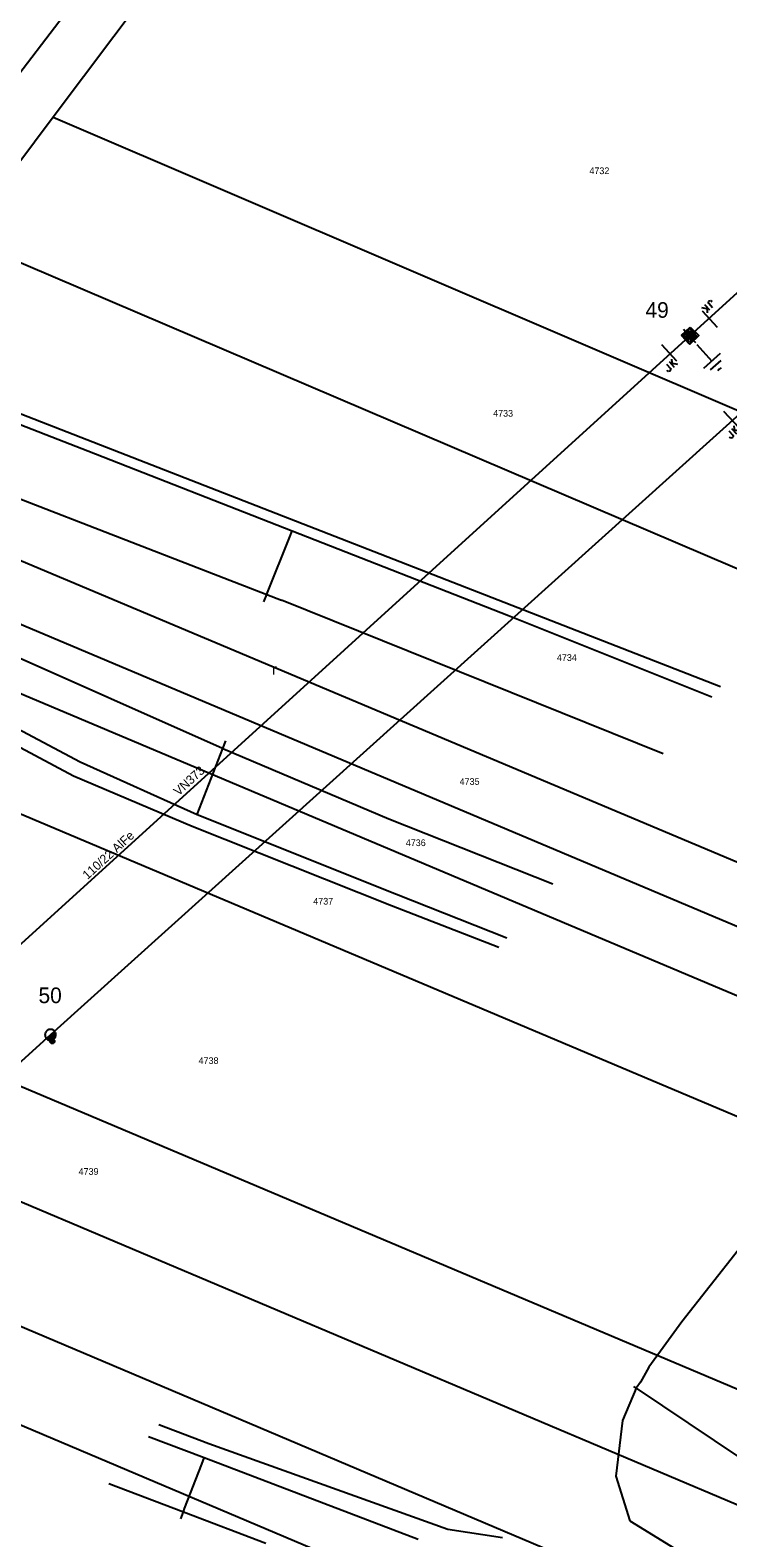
# Model space of a CAD drawing. Extents: x -540150 to -533593, y -1185082 to -1180066.
# Drawn here: x -536094 to -536015.9, y -1182345.7 to -1182176.7 of the extents above; entities that cross this region are included whole.
import ezdxf

# ---------------------------------------------------------------- set-up
doc = ezdxf.new("R2010")
doc.units = 0
for name, color, linetype in [('KN_HRAN_PARCEL', 7, 'Continuous'), ('KN_PARC_Č', 7, 'Continuous'), ('Vrstva 1', 7, 'Continuous'), ('Vrstva 13', 7, 'Continuous'), ('Vrstva 14', 7, 'Continuous'), ('Vrstva 15', 7, 'Continuous'), ('Vrstva 18', 7, 'Continuous'), ('Vrstva 2', 7, 'Continuous'), ('Vrstva 25', 7, 'Continuous'), ('Vrstva 3', 7, 'Continuous'), ('Vrstva 36', 7, 'Continuous'), ('Vrstva 7', 7, 'Continuous')]:
    doc.layers.add(name, color=color, linetype=linetype)

# ---------------------------------------------------------------- blocks, each defined once
blk = doc.blocks.new('VN840')
at = {"layer": 'Vrstva 15'}
for points in [[(-0.01, 1.41), (-0.01, -1.09)], [(-1.51, -1.24), (-1.51, -1.15)], [(-1.48, -1.35), (-1.51, -1.24)], [(-1.33, -1.42), (-1.48, -1.35)], [(-1.27, -1.42), (-1.33, -1.42)], [(-1.13, -1.35), (-1.27, -1.42)], [(-1.09, -1.24), (-1.13, -1.35)], [(-1.09, -0.59), (-1.09, -1.24)], [(-0.68, -0.59), (-0.68, -1.42)], [(-0.68, -1.11), (-0.27, -0.59)], [(-0.54, -0.94), (-0.2, -1.42)]]:
    blk.add_lwpolyline(points, dxfattribs=at)
blk = doc.blocks.new('VN440')
at = {"layer": 'Vrstva 2'}
for points in [[(1.22, 0), (1.21, 0.13), (1.19, 0.25), (1.16, 0.38), (1.11, 0.5), (1.05, 0.61), (0.98, 0.72), (0.9, 0.82), (0.81, 0.91), (0.71, 0.99), (0.6, 1.06), (0.49, 1.12), (0.37, 1.16), (0.25, 1.2), (0.12, 1.22), (-0.01, 1.22), (-0.14, 1.22), (-0.26, 1.2), (-0.39, 1.16), (-0.51, 1.12), (-0.62, 1.06), (-0.73, 0.99), (-0.83, 0.91), (-0.92, 0.82), (-1, 0.72), (-1.07, 0.61), (-1.13, 0.5), (-1.18, 0.38), (-1.21, 0.25), (-1.23, 0.13), (-1.24, 0), (-1.23, -0.13), (-1.21, -0.26), (-1.18, -0.38), (-1.13, -0.5), (-1.07, -0.62), (-1, -0.73), (-0.92, -0.83), (-0.83, -0.92), (-0.73, -1), (-0.62, -1.07), (-0.51, -1.13), (-0.39, -1.17), (-0.26, -1.2), (-0.14, -1.23), (-0.01, -1.23), (0.12, -1.23), (0.25, -1.2), (0.37, -1.17), (0.49, -1.13), (0.6, -1.07), (0.71, -1), (0.81, -0.92), (0.9, -0.83), (0.98, -0.73), (1.05, -0.62), (1.11, -0.5), (1.16, -0.38), (1.19, -0.26), (1.21, -0.13), (1.22, 0)], [(-1.24, 0), (1.22, 0)], [(-1.18, -0.34), (1.1, -0.34)], [(-1.01, -0.63), (0.97, -0.63)], [(-0.74, -0.92), (0.68, -0.92)]]:
    blk.add_lwpolyline(points, dxfattribs=at)
blk = doc.blocks.new('VN810')
at = {"layer": 'Vrstva 14'}
for points in [[(0, -1.25), (0, -3.75)], [(1.25, -3.75), (-1.25, -3.75)], [(0.77, -4.37), (-0.8, -4.37)], [(0, -5), (-0.25, -5)], [(0.27, -5), (0, -5)]]:
    blk.add_lwpolyline(points, dxfattribs=at)
blk = doc.blocks.new('VN470')
at = {"layer": 'Vrstva 2'}
for points in [[(-1.23, 1.22), (1.23, 1.22)], [(-1.23, -1.23), (-1.23, 1.22)], [(-0.92, 0.9), (0.92, 0.9)], [(-0.92, -0.95), (-0.92, 0.9)], [(-0.61, 0.61), (0.61, 0.61)], [(-0.61, -0.62), (-0.61, 0.61)], [(-0.31, -0.27), (-0.31, 0.34)], [(-0.31, 0.34), (0.31, 0.34)], [(0, 1.22), (0, 1.97)], [(0.31, 0.34), (0.31, -0.27)], [(0.61, 0.61), (0.61, -0.62)], [(0.92, 0.9), (0.92, -0.95)], [(1.23, 1.22), (1.23, -1.23)], [(1.23, -1.23), (-1.23, -1.23)], [(0.92, -0.95), (-0.92, -0.95)], [(0.61, -0.62), (-0.61, -0.62)], [(0.31, -0.27), (-0.31, -0.27)], [(0, -1.23), (0, -1.98)]]:
    blk.add_lwpolyline(points, dxfattribs=at)

msp = doc.modelspace()

# ---------------------------------------------------------------- linework, layer by layer
at = {"layer": 'KN_HRAN_PARCEL'}
for p, q in [((-536075.77, -1182165.61), (-536091.46, -1182186.49)), ((-536091.46, -1182186.49), (-536101.6, -1182200.04)), ((-536091.46, -1182186.49), (-535990.58, -1182229.75)), ((-536101.6, -1182200.04), (-535965.35, -1182258.21)), ((-536120.65, -1182225.43), (-535972.96, -1182287.61)), ((-536124.53, -1182230.88), (-535974.77, -1182294.08)), ((-536129.02, -1182236.75), (-535976.56, -1182301.1)), ((-536136.67, -1182246.99), (-535979.71, -1182313.28)), ((-536154.1, -1182270.11), (-535986.76, -1182340.88)), ((-535989.8, -1182352.58), (-536161.48, -1182279.94)), ((-536169.4, -1182290.52), (-535993.07, -1182365.17)), ((-536175.67, -1182298.88), (-535995.6, -1182375.13))]:
    msp.add_line(p, q, dxfattribs=at)
at = {"layer": 'Vrstva 1'}
for points in [[(-535558.37, -1181516.47), (-535557.88, -1181544.08), (-535587.84, -1181626.35), (-535619.52, -1181709.12), (-535651.77, -1181794.03), (-535681.12, -1181869.54), (-535710.09, -1181945.05), (-535783.95, -1182011.48), (-535866.19, -1182086.36), (-535938.34, -1182149.87), (-536013.11, -1182218.39), (-536091.77, -1182289.3), (-536171.39, -1182361.64), (-536250.64, -1182434.05), (-536331.09, -1182507.05), (-536410.34, -1182579.17), (-536496.48, -1182657.64), (-536561.1, -1182716.88), (-536627.07, -1182777.54), (-536686.64, -1182832.24), (-536719.16, -1182861.03)], [(-536097.51, -1182281.3), (-536020.22, -1182211.02), (-535949.21, -1182146.34), (-535873.11, -1182077.36)]]:
    msp.add_lwpolyline(points, dxfattribs=at)
at = {"layer": 'Vrstva 14'}
for p, q in [((-536101.68, -1182189.98), (-536088.77, -1182173.09)), ((-536109.43, -1182215.35), (-536087.58, -1182223.88)), ((-536087.58, -1182223.88), (-536064.7, -1182232.83)), ((-536064.7, -1182232.83), (-536040.49, -1182242.34)), ((-536067.89, -1182240.81), (-536067.56, -1182239.98)), ((-536067.56, -1182239.98), (-536067.47, -1182239.75)), ((-536108.96, -1182240.97), (-536072.51, -1182257.2)), ((-536040.49, -1182242.34), (-536017.72, -1182251.43)), ((-536100.05, -1182252.56), (-536088.45, -1182258.71)), ((-536089.2, -1182260.31), (-536100.91, -1182254.06)), ((-536072.46, -1182257.22), (-536072.13, -1182256.36)), ((-536088.45, -1182258.71), (-536075.36, -1182264.63)), ((-536075.92, -1182265.97), (-536089.2, -1182260.31)), ((-536075.36, -1182264.63), (-536053.03, -1182273.54)), ((-536053.89, -1182265.1), (-536035.51, -1182272.37)), ((-536053.58, -1182274.87), (-536075.92, -1182265.97)), ((-536053.03, -1182273.54), (-536040.67, -1182278.45)), ((-536041.59, -1182279.53), (-536053.58, -1182274.87)), ((-536022.87, -1182323.92), (-536024.77, -1182326.53)), ((-536026.2, -1182328.9), (-536027.72, -1182332.52)), ((-536079.65, -1182332.96), (-536074.03, -1182335.09)), ((-536027.72, -1182332.52), (-536028.47, -1182338.74)), ((-536074.56, -1182336.7), (-536080.81, -1182334.33)), ((-536074.03, -1182335.09), (-536047.3, -1182344.7)), ((-536050.61, -1182345.86), (-536074.56, -1182336.7)), ((-536028.47, -1182338.74), (-536026.91, -1182343.76)), ((-536077.19, -1182343.51), (-536076.89, -1182342.73)), ((-536076.89, -1182342.73), (-536076.76, -1182342.38)), ((-536047.3, -1182344.7), (-536041.16, -1182345.63)), ((-536026.91, -1182343.76), (-536021.37, -1182347.16))]:
    msp.add_line(p, q, dxfattribs=at)
for points in [[(-536140.4, -1182211.72), (-536112.24, -1182222.65), (-536067.56, -1182239.98), (-536065.92, -1182240.61)], [(-536108.24, -1182214.6), (-536016.74, -1182250.27)], [(-536067.47, -1182239.75), (-536064.97, -1182233.53), (-536064.7, -1182232.83)], [(-536023.16, -1182257.82), (-536065.92, -1182240.61)], [(-536075.36, -1182264.63), (-536075.07, -1182263.94), (-536072.46, -1182257.22)], [(-536072.51, -1182257.2), (-536072.46, -1182257.22), (-536053.89, -1182265.1)], [(-536014.74, -1182313.39), (-536021.09, -1182321.46), (-536022.87, -1182323.92)], [(-536024.77, -1182326.53), (-536025.71, -1182328.2), (-536026.2, -1182328.9)], [(-536026.48, -1182328.72), (-536026.23, -1182328.89), (-536026.2, -1182328.9), (-536014.51, -1182336.74)], [(-536076.76, -1182342.38), (-536074.83, -1182337.4), (-536074.56, -1182336.7)], [(-536085.25, -1182339.55), (-536076.89, -1182342.73), (-536067.67, -1182346.24)]]:
    msp.add_lwpolyline(points, dxfattribs=at)
at = {"layer": 'Vrstva 25'}
for points in [[(-536020.52, -1182210.93), (-536020.18, -1182211.29), (-536019.82, -1182210.95), (-536020.16, -1182210.59)], [(-536020.45, -1182210.94), (-536020.17, -1182211.22), (-536019.89, -1182210.95), (-536020.16, -1182210.66)], [(-536020.38, -1182210.94), (-536020.17, -1182211.15), (-536019.96, -1182210.94), (-536020.17, -1182210.73)], [(-536020.31, -1182210.94), (-536020.17, -1182211.08), (-536020.03, -1182210.94), (-536020.17, -1182210.8)], [(-536020.24, -1182210.94), (-536020.17, -1182211.01), (-536020.1, -1182210.94), (-536020.17, -1182210.87)]]:
    msp.add_lwpolyline(points, close=True, dxfattribs=at)
for radius in [0.25, 0.2, 0.15, 0.1, 0.05]:
    msp.add_circle((-536091.56, -1182290.04), radius, dxfattribs=at)
at = {"layer": 'Vrstva 7'}
msp.add_lwpolyline([(-536020.16, -1182210.02), (-536019.19, -1182210.97), (-536020.18, -1182211.93), (-536021.11, -1182210.91), (-536020.16, -1182210.02)], dxfattribs=at)

# ---------------------------------------------------------------- block references
at = {"layer": 'Vrstva 13'}
for name, p, xscale, yscale, rotation in [('VN470', (-536020.22, -1182211.02), 0.49999999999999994, 0.5000000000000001, 42.32633901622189), ('VN440', (-536091.77, -1182289.3), 0.5000000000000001, 0.5, 41.53399159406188)]:
    msp.add_blockref(name, p, dxfattribs=dict(at, xscale=xscale, yscale=yscale, rotation=rotation))
at = {"layer": 'Vrstva 15', "rotation": 41.84299170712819}
msp.add_blockref('VN810', (-536020.22, -1182211.02), dxfattribs=at)
at = {"layer": 'Vrstva 18'}
for p, rotation in [((-536018.04, -1182209.03), -137.67366108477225), ((-536022.39, -1182212.99), 42.281988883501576), ((-536015.43, -1182220.47), 43.137561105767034)]:
    msp.add_blockref('VN840', p, dxfattribs=dict(at, rotation=rotation))

# ---------------------------------------------------------------- texts
at = {"layer": 'KN_PARC_Č'}
for s, p in [('4732', (-536031.43, -1182192.88)), ('4733', (-536042.21, -1182220.05)), ('4734', (-536035.07, -1182247.41)), ('4735', (-536045.96, -1182261.3)), ('4736', (-536051.99, -1182268.16)), ('4737', (-536062.35, -1182274.71)), ('4738', (-536075.19, -1182292.57)), ('4739', (-536088.62, -1182304.99))]:
    msp.add_text(s, height=0.75, dxfattribs=at).set_placement(p)
at = {"layer": 'Vrstva 14'}
for s, p in [('49', (-536025.15, -1182208.97)), ('50', (-536093.11, -1182285.75))]:
    msp.add_text(s, height=1.75, dxfattribs=at).set_placement(p)
at = {"layer": 'Vrstva 2'}
msp.add_text('110/22 AlFe', height=1, rotation=42.282, dxfattribs=at).set_placement((-536087.63, -1182271.96))
at = {"layer": 'Vrstva 3'}
msp.add_text('VN373', height=1, rotation=42.282, dxfattribs=at).set_placement((-536077.43, -1182262.58))
at = {"layer": 'Vrstva 36'}
msp.add_text('r', height=1.2, dxfattribs=at).set_placement((-536066.97, -1182248.94))

doc.saveas('drawing.dxf')
